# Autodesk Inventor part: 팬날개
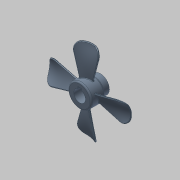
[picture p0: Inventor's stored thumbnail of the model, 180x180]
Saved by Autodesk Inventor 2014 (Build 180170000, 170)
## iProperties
Company: 한국ATC센터
Created: 2016-06
Part Number: 팬날개
Document SubType Name: Modeling
Designer: mdu
Density: 1.06 g/cm^3
Material: ABS 플라스틱
Mass: 26.249 g
Surface Area: 149.779 cm^2
Volume: 24.7632 cm^3
Appearance: 강청색
Author: mdu
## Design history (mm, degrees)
sketch "스케치1"
  geometry: L1 (-15, 0)-(15, 0); L2 (-15, 0)-(-15, 17); L3 (-15, 17)-(5, 17); L4 (5, 17)-(5, 13); L5 (5, 13)-(15, 13); L6 (15, 13)-(15, 0); 2 further points
  constraints: 12 end point, 3 parallel, 2 perpendicular, 1 coincident, 1 horizontal, 1 midpoint
  dimensions: "d0" = 30 distance of L1.start L1.end; "d8" = 34 diameter of L3 L1; "d10" = 26 diameter of L5 L1; "d32" = 20 distance of L2.end L3.end
revolve "회전1" sketch "스케치1" stored, may be unused: angle "d11" = 90 deg
node "작업 평면2"
sketch "스케치7"
  geometry: L1 (-15, 17)-(5, 17) reference; L2 (-15, -17)-(5, -17) reference; L3 (-5, 17)-(-5, -17); A1 r 35 centre (-36.399, -13.457) between (-2, -7) and (-8, 7); 1 further point
  constraints: 2 end point, 2 midpoint, 2 point on circle, 1 centre point
  dimensions: "d36" = 35 radius of A1; "d37" = 10 distance from line of A1.start L2; "d38" = 10 distance from line of A1.end L1; "d45" = 3 distance from line of A1.end L3; "d46" = 3 distance from line of A1.start L3
sketch "3D 스케치1"
  geometry: L1 through (0, 0) direction (1, 0) reference; L2 through (0, 0) direction (1, 0) reference; 13 other entities
  constraints: 2 collinear
  node "투영 원본 위치 스케치7"
sketch "스케치8"
  geometry: L1 (-15, 17)-(5, 17) reference; L2 (-15, -17)-(5, -17) reference; L3 (-5, 17)-(-5, -17); A1 r 30 centre (-28.74, -3.591) between (-3, -19) and (-9, 19); 1 further point
  constraints: 2 end point, 2 midpoint, 2 point on circle, 1 centre point
  dimensions: "d43" = 30 radius of A1; "d47" = 4 distance from line of A1.end L3; "d48" = 2 distance from line of A1.start L3; "d58" = 2 distance from line of A1.end L1; "d59" = 2 distance from line of A1.start L2
sketch "3D 스케치2"
sketch "3D 스케치3"
feature "경계 패치1" sketch "3D 스케치2", "3D 스케치3" dims "d50" = 0
feature "연장1" dims "d55" = 2
feature "두껍게 하기1" dims "d51" = 2, "d52" = 2
sketch "스케치9"
  geometry: C1 r 59 at (0, 0); 1 further point
  constraints: 1 centre point, 1 coincident
  dimensions: "d60" = 118 diameter of C1
extrude "돌출2" sketch "스케치9" distance "d62" = 200; taper "d63" = 0 deg
fillet "모깎기6" dims "d64" = 10
fillet "모깎기7" dims "d66" = 0.8
fillet "모깎기8" dims "d67" = 0.8
sketch "스케치2"
  geometry: L1 (-2.5, 8.124)-(-2.5, 10.8); L2 (-2.5, 10.8)-(2.5, 10.8); L3 (2.5, 10.8)-(2.5, 8.124); A1 r 8.5 centre (0, 0) between (-2.5, 8.124) and (2.5, 8.124); 1 further point
  constraints: 6 end point, 2 parallel, 2 point on circle, 1 centre point, 1 coincident, 1 horizontal, 1 vertical
  dimensions: "d12" = 17 diameter of A1; "d13" = 5 distance of L1.end L2.end; "d14" = 19.3 dimension on A1 L2 (computed from d12)
extrude "돌출1" cut sketch "스케치2" stored distance "d15" = 10; taper "d16" = 0 deg
chamfer "모따기1" distance "d17" = 1; stored, may be unused: second distance "d18" = 2, angle "d19" = 45 deg
node "작업 평면1"
sketch "스케치3"
  geometry: L1 (5, -13)-(5, 13) reference; 3 further points
  constraints: 1 horizontal alignment, 1 midpoint
  dimensions: "d20" = 5 distance from line of L1 point (0, 0)
hole "구멍1" sketch "스케치3" at (0, 0) diameter "d21" = 3.242; stored, may be unused: countersink angle "d25" = 90 deg, drill point angle "d27" = 118 deg; dims "d22" = 6, "d23" = 4, "d24" = 2, "d26" = 8
fillet "모깎기9" dims "d77" = 2
fillet "모깎기10" dims "d78" = 2
fillet "모깎기11" dims "d79" = 2
node "솔리드1"
pattern_circular "원형 패턴1" dims "d69" = 360 deg
pattern_circular "원형 패턴2" dims angle "d72" = 360 deg
pattern_circular "원형 패턴3" dims angle "d75" = 360 deg
node "투영 원본 위치 스케치8"
node "곡면1"
node "곡면2"
node "곡면3"
node "곡면4"
feature "경계 패치2"
feature "경계 패치3"
feature "경계 패치4"
